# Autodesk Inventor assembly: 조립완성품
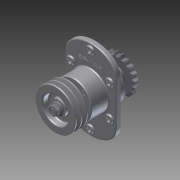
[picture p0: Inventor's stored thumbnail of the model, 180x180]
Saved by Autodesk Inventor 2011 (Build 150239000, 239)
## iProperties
Created: 2015-02
Part Number: 조립완성품
Document SubType Name: Assembly
Designer: LINEART07
Author: LINEART07
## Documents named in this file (11)
- C:\Users\LINEART07\Desktop\450207v1018\답안조립품.iam
- C:\Users\LINEART07\Desktop\450207v1018\1-본체.ipt
- C:\Users\LINEART07\Desktop\450207v1018\6-베어링 6206.ipt
- C:\Users\LINEART07\Desktop\450207v1018\2-커버.ipt
- C:\Users\LINEART07\Desktop\450207v1018\3-축.ipt
- C:\Users\LINEART07\Desktop\450207v1018\8-오일실 30x42.ipt
- C:\Users\LINEART07\Desktop\450207v1018\11-키 6x6.ipt
- C:\Users\LINEART07\Desktop\450207v1018\4-V벨트풀리.ipt
- C:\Users\LINEART07\Desktop\450207v1018\9-M16-너트.ipt
- C:\Users\LINEART07\Desktop\450207v1018\5-체인 스프로킷.ipt
- C:\Users\LINEART07\Desktop\450207v1018\10-M6.ipt
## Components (22 placed, 10 different names)
1. 1-본체:1 — 각도:4, 각도:6, 각도:7, 각도:8
2. 6-베어링 6206:1
3. 6-베어링 6206:2
4. 2-커버:1
5. 3-축:1 — 각도:1, 각도:2
6. 2-커버:2
7. 8-8-오일실 30x42:1
8. 8-8-오일실 30x42:2
9. 11-키 6x6:1 — 각도:1, 각도:3
10. 11-키 6x6:2 — 각도:2, 각도:5
11. 4-V벨트풀리:1 — 각도:3
12. 9-M16 너트:1 — 각도:4
13. 5-체인 스프로킷:1 — 각도:5
14. 9-M16 너트:2 — 각도:6
15. 10-M6:1 — 각도:8
16. 10-M6:3
17. 10-M6:4
18. 10-M6:5
19. 10-M6:2 — 각도:7
20. 10-M6:6
21. 10-M6:7
22. 10-M6:8
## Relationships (8: Angle 8)
- 각도:1 [Angle]: 3-축:1 ↔ 11-키 6x6:1
- 각도:2 [Angle]: 3-축:1 ↔ 11-키 6x6:2
- 각도:3 [Angle]: 11-키 6x6:1 ↔ 4-V벨트풀리:1
- 각도:4 [Angle]: 1-본체:1 ↔ 9-M16 너트:1
- 각도:5 [Angle]: 11-키 6x6:2 ↔ 5-체인 스프로킷:1
- 각도:6 [Angle]: 1-본체:1 ↔ 9-M16 너트:2
- 각도:7 [Angle]: 1-본체:1 ↔ 10-M6:2
- 각도:8 [Angle]: 1-본체:1 ↔ 10-M6:1
